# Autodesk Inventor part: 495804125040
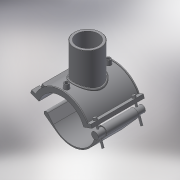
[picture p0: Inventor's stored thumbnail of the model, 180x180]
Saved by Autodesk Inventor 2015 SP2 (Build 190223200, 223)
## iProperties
Created: 2017-07
Part Number: 495804125040
Material: Generic
Description: PLASSON BRANCH SADDLE 125-40
Document SubType Name: Modeling
Designer: KIM
Density: 1 g/cm^3
Appearance: Default
Author: KIM
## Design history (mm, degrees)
derived "495804.ipt"
feature "Solid1::495804.ipt"
feature "Solid2::495804.ipt"
tag "TaggingFeature1"
body "Solid1"
body "Solid2"
other parameters: "d0" = 125, "d2" = 162, "d3" = 31.25, "d4" = 118, "d5" = 0, "d6" = 0.1, "d8" = 0, "d19" = 6, "d20" = 6, "d21" = 70.8, "d23" = 0, "d24" = 35.4, "d26" = 0, "d27" = 3, "d28" = 3, "d29" = 3, "d30" = 41.66667, "d31" = 6, "d32" = 0, "d33" = 0, "d34" = 0.6, "d40" = 75.4, "d41" = 44, "d43" = 0, "d45" = 0, "d47" = 150.5, "d50" = 0, "d70" = 15, "d72" = 0, "d73" = 6, "d75" = 5, "d76" = 0, "d77" = 6.25, "d78" = 92.5, "d79" = 15, "d80" = 47.2, "d82" = 5 deg, "d84" = 4, "d85" = 14, "d86" = 0, "d87" = 3, "d88" = 0, "d89" = 1, "d90" = 1, "d91" = 94.4, "d92" = 0, "d93" = 0.5, "d94" = 65.78947, "d96" = 147.9, "d97" = 2.36, "d98" = 0, "d102" = 1.2, "d103" = 32, "d105" = 0, "d109" = -26, "d117" = 0.4, "d120" = 140 deg, "d121" = 24.228, "d122" = 20 deg, "d124" = 87, "d126" = 0, "d143" = 131.25, "d150" = 22.5, "d159" = 4, "d161" = 3.125, "d162" = 70.8, "d163" = 0, "d167" = 25, "d168" = 65.90909, "d173" = 1, "d175" = 62.5, "d176" = 20 deg, "d177" = 8.75, "d180" = 0, "d185" = 38.35, "d186" = 38.35, "d187" = 72.5, "d188" = 6, "d189" = 8.75, "d190" = 0, "d191" = 108.75, "d202" = 0, "d216" = 106.2, "d217" = 0, "d221" = 43.66, "d222" = 8.75, "d223" = 5.25, "d224" = 62.5, "d225" = 5.25, "d227" = 18, "d230" = 77.5, "d236" = 20 deg, "d237" = 79.5, "d238" = 20 deg, "d239" = 8.75, "d_" = 125, "B_" = 162, "H_" = 78, "L_" = 118, "d_t" = 6, "H_1" = 68, "d1" = 145, "d148" = 3.125, "d160" = 3.125
